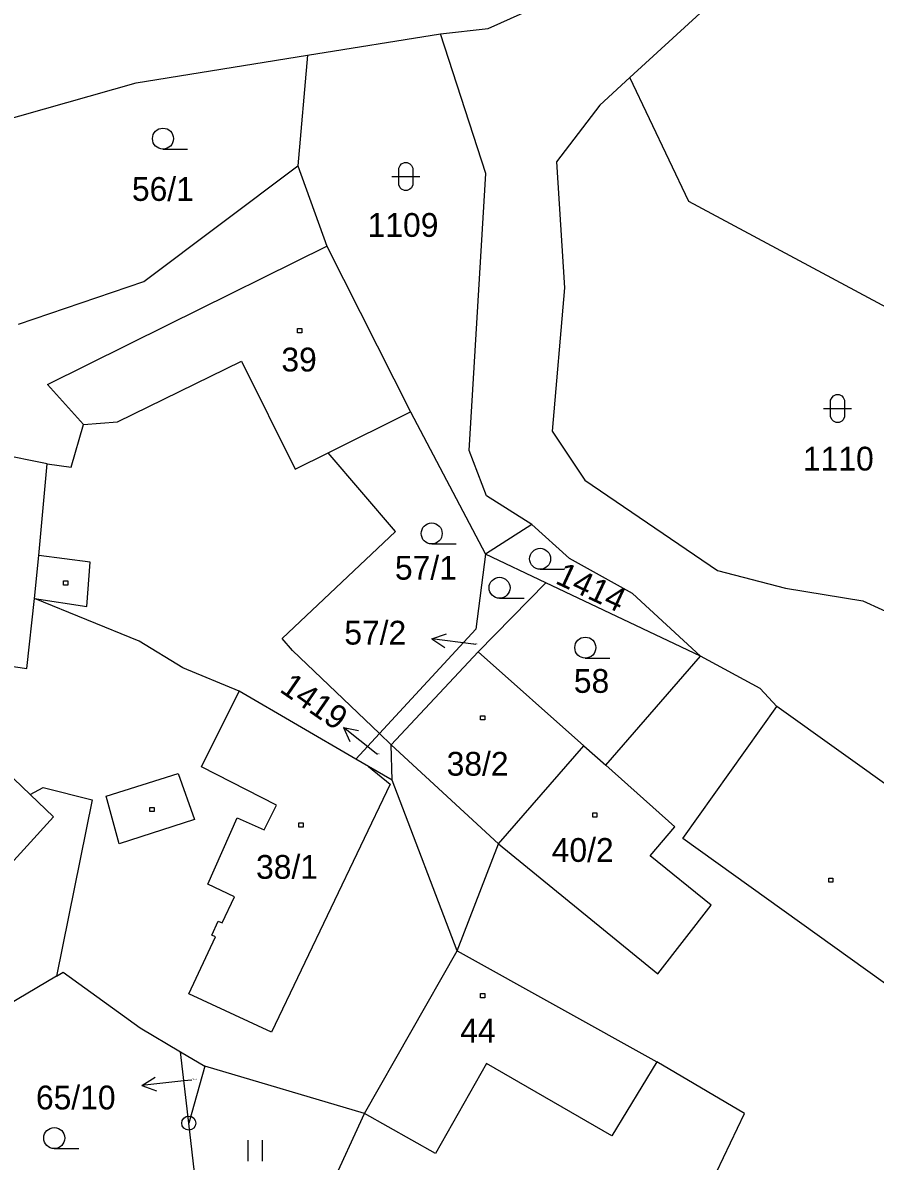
# Model space of a CAD drawing. Extents: x -796130 to -793145, y -1109506 to -1106267.
# Drawn here: x -794380.3 to -794319.4, y -1107911.5 to -1107830.1 of the extents above; entities that cross this region are included whole.
import ezdxf

# ---------------------------------------------------------------- set-up
doc = ezdxf.new("R2010")
doc.units = 0
for name, color, linetype in [('Komunikace', 7, 'Continuous'), ('Vrstva 1', 7, 'Continuous'), ('Vrstva 14', 7, 'Continuous'), ('Vrstva 15', 7, 'Continuous'), ('Vrstva 16', 7, 'Continuous'), ('Vrstva 2', 7, 'Continuous'), ('Vrstva 23', 7, 'Continuous'), ('Vrstva 25', 7, 'Continuous'), ('Vrstva 28', 7, 'Continuous')]:
    doc.layers.add(name, color=color, linetype=linetype)

msp = doc.modelspace()

# ---------------------------------------------------------------- linework, layer by layer
at = {"layer": 'Komunikace'}
for p, q in [((-794347.96, -1107874.54), (-794348.14, -1107874.52)), ((-794354.99, -1107882.39), (-794355.08, -1107882.32)), ((-794368.26, -1107905.67), (-794368.84, -1107905.73))]:
    msp.add_line(p, q, dxfattribs=at)
at = {"layer": 'Vrstva 1'}
for p, q in [((-794347.08, -1107830.5), (-794344.59, -1107829.39)), ((-794331.93, -1107829.42), (-794336.96, -1107834.02)), ((-794350.48, -1107830.89), (-794347.08, -1107830.5)), ((-794359.99, -1107832.42), (-794350.48, -1107830.89)), ((-794347.26, -1107840.88), (-794350.48, -1107830.89)), ((-794372.24, -1107834.39), (-794359.99, -1107832.42)), ((-794359.99, -1107832.42), (-794360.69, -1107840.33)), ((-794336.96, -1107834.02), (-794339.11, -1107835.98)), ((-794332.74, -1107842.87), (-794336.96, -1107834.02)), ((-794387.13, -1107838.61), (-794372.24, -1107834.39)), ((-794339.11, -1107835.98), (-794342.2, -1107840.04)), ((-794371.7, -1107848.58), (-794360.69, -1107840.33)), ((-794360.69, -1107840.33), (-794358.61, -1107846.07)), ((-794342.2, -1107840.04), (-794341.63, -1107849.04)), ((-794348.44, -1107860.66), (-794347.26, -1107840.88)), ((-794317.46, -1107851.08), (-794332.74, -1107842.87)), ((-794369.98, -1107851.7), (-794358.61, -1107846.07)), ((-794358.61, -1107846.07), (-794352.64, -1107857.91)), ((-794380.64, -1107851.64), (-794371.7, -1107848.58)), ((-794341.63, -1107849.04), (-794342.51, -1107859.28)), ((-794378.57, -1107855.95), (-794369.98, -1107851.7)), ((-794375.99, -1107858.82), (-794378.57, -1107855.95)), ((-794358.52, -1107860.84), (-794352.64, -1107857.91)), ((-794352.64, -1107857.91), (-794347.28, -1107868.09)), ((-794376.89, -1107861.87), (-794375.99, -1107858.82)), ((-794378.6, -1107861.62), (-794387.41, -1107859.84)), ((-794342.51, -1107859.28), (-794340.17, -1107862.78)), ((-794353.71, -1107866.47), (-794358.52, -1107860.84)), ((-794347.2, -1107863.9), (-794348.44, -1107860.66)), ((-794379.19, -1107868.18), (-794378.6, -1107861.62)), ((-794378.6, -1107861.62), (-794376.89, -1107861.87)), ((-794340.17, -1107862.78), (-794330.69, -1107869.24)), ((-794343.96, -1107865.95), (-794347.2, -1107863.9)), ((-794361.8, -1107874.11), (-794353.71, -1107866.47)), ((-794343.96, -1107865.95), (-794347.28, -1107868.09)), ((-794341.28, -1107868.4), (-794343.96, -1107865.95)), ((-794379.5, -1107871.25), (-794379.19, -1107868.18)), ((-794342.97, -1107870.13), (-794347.28, -1107868.09)), ((-794336.76, -1107870.88), (-794341.28, -1107868.4)), ((-794330.69, -1107869.24), (-794325.84, -1107870.51)), ((-794347.79, -1107875.06), (-794342.97, -1107870.13)), ((-794331.92, -1107875.38), (-794342.97, -1107870.13)), ((-794325.84, -1107870.51), (-794320.31, -1107871.41)), ((-794380.04, -1107876.26), (-794379.5, -1107871.25)), ((-794372.02, -1107874.29), (-794379.5, -1107871.25)), ((-794331.92, -1107875.38), (-794336.76, -1107870.88)), ((-794320.31, -1107871.41), (-794314.42, -1107874.11)), ((-794368.91, -1107876.2), (-794372.02, -1107874.29)), ((-794361.07, -1107874.97), (-794361.8, -1107874.11)), ((-794387.27, -1107875.15), (-794380.04, -1107876.26)), ((-794354.84, -1107880.9), (-794361.07, -1107874.97)), ((-794354.01, -1107881.7), (-794347.79, -1107875.06)), ((-794347.79, -1107875.06), (-794340.25, -1107881.77)), ((-794338.68, -1107883.17), (-794331.92, -1107875.38)), ((-794327.64, -1107877.67), (-794331.92, -1107875.38)), ((-794379.8, -1107885.26), (-794389.2, -1107876.29)), ((-794364.88, -1107877.88), (-794368.91, -1107876.2)), ((-794356.53, -1107882.73), (-794364.88, -1107877.88)), ((-794326.45, -1107878.97), (-794327.64, -1107877.67)), ((-794316.94, -1107885.78), (-794326.45, -1107878.97)), ((-794354.84, -1107880.9), (-794356.53, -1107882.73)), ((-794354.01, -1107881.7), (-794354.84, -1107880.9)), ((-794353.95, -1107884.23), (-794354.01, -1107881.7)), ((-794346.35, -1107888.77), (-794340.25, -1107881.77)), ((-794340.25, -1107881.77), (-794338.68, -1107883.17)), ((-794355.63, -1107883.26), (-794356.53, -1107882.73)), ((-794353.95, -1107884.23), (-794355.63, -1107883.26)), ((-794349.3, -1107896.42), (-794353.95, -1107884.23)), ((-794379.8, -1107885.26), (-794378.88, -1107884.76)), ((-794378.88, -1107884.76), (-794375.38, -1107885.63)), ((-794375.38, -1107885.63), (-794377.92, -1107898.25)), ((-794349.3, -1107896.42), (-794346.35, -1107888.77)), ((-794355.91, -1107908.06), (-794349.3, -1107896.42)), ((-794349.3, -1107896.42), (-794335.04, -1107904.37)), ((-794377.92, -1107898.25), (-794383.71, -1107901.64)), ((-794377.92, -1107898.25), (-794377.45, -1107897.95)), ((-794377.45, -1107897.95), (-794371.95, -1107901.93)), ((-794371.95, -1107901.93), (-794369.07, -1107903.65)), ((-794368.48, -1107908.74), (-794369.07, -1107903.65)), ((-794369.07, -1107903.65), (-794367.34, -1107904.68)), ((-794367.34, -1107904.68), (-794368.48, -1107908.74)), ((-794355.91, -1107908.06), (-794367.34, -1107904.68)), ((-794328.77, -1107908.05), (-794335.04, -1107904.37)), ((-794360.32, -1107917.58), (-794355.91, -1107908.06)), ((-794332.4, -1107915.66), (-794328.77, -1107908.05))]:
    msp.add_line(p, q, dxfattribs=at)
for points in [[(-794347.28, -1107868.09), (-794347.96, -1107873.45), (-794354.84, -1107880.9)], [(-794370.64, -1107920.8), (-794367.05, -1107921.18), (-794368.48, -1107908.74)]]:
    msp.add_lwpolyline(points, dxfattribs=at)
at = {"layer": 'Vrstva 16'}
for p, q in [((-794351.115, -1107874.135), (-794350.059, -1107873.768)), ((-794348.14, -1107874.52), (-794351.115, -1107874.135)), ((-794351.115, -1107874.135), (-794350.187, -1107874.759)), ((-794355.08, -1107882.32), (-794357.431, -1107880.457)), ((-794357.431, -1107880.457), (-794356.958, -1107881.47)), ((-794357.431, -1107880.457), (-794356.337, -1107880.686)), ((-794371.822, -1107906.056), (-794370.882, -1107905.45)), ((-794368.84, -1107905.73), (-794371.822, -1107906.056)), ((-794371.822, -1107906.056), (-794370.773, -1107906.444))]:
    msp.add_line(p, q, dxfattribs=at)
at = {"layer": 'Vrstva 2'}
for p, q in [((-794373.57, -1107858.63), (-794364.7, -1107854.28)), ((-794364.7, -1107854.28), (-794360.87, -1107862.01)), ((-794375.99, -1107858.82), (-794373.57, -1107858.63)), ((-794360.87, -1107862.01), (-794358.52, -1107860.84)), ((-794375.52, -1107868.66), (-794379.19, -1107868.18)), ((-794375.77, -1107871.81), (-794375.52, -1107868.66)), ((-794379.5, -1107871.25), (-794375.77, -1107871.81)), ((-794367.57, -1107883.28), (-794364.88, -1107877.88)), ((-794333.17, -1107888.4), (-794326.45, -1107878.97)), ((-794346.35, -1107888.77), (-794354.01, -1107881.7)), ((-794362.2, -1107886.02), (-794367.57, -1107883.28)), ((-794355.63, -1107883.26), (-794354.08, -1107884.51)), ((-794333.74, -1107887.56), (-794338.68, -1107883.17)), ((-794374.38, -1107885.37), (-794369.23, -1107883.76)), ((-794369.23, -1107883.76), (-794368.07, -1107887.05)), ((-794378.14, -1107886.86), (-794379.8, -1107885.26)), ((-794354.08, -1107884.51), (-794362.57, -1107902.25)), ((-794373.45, -1107888.77), (-794374.38, -1107885.37)), ((-794363.1, -1107887.78), (-794362.2, -1107886.02)), ((-794383.35, -1107892.55), (-794378.14, -1107886.86)), ((-794368.07, -1107887.05), (-794373.45, -1107888.77)), ((-794367.11, -1107891.66), (-794365.01, -1107886.93)), ((-794365.01, -1107886.93), (-794363.1, -1107887.78)), ((-794335.51, -1107889.65), (-794333.74, -1107887.56)), ((-794312.5, -1107903.24), (-794333.17, -1107888.4)), ((-794346.35, -1107888.77), (-794334.95, -1107898.06)), ((-794331.15, -1107893.16), (-794335.51, -1107889.65)), ((-794365.2, -1107892.56), (-794367.11, -1107891.66)), ((-794366.08, -1107894.43), (-794365.2, -1107892.56)), ((-794334.95, -1107898.06), (-794331.15, -1107893.16)), ((-794366.84, -1107895.3), (-794366.37, -1107894.3)), ((-794366.37, -1107894.3), (-794366.08, -1107894.43)), ((-794368.47, -1107899.49), (-794366.56, -1107895.43)), ((-794366.56, -1107895.43), (-794366.84, -1107895.3)), ((-794362.57, -1107902.25), (-794368.47, -1107899.49)), ((-794347.21, -1107904.49), (-794350.84, -1107910.91)), ((-794338.24, -1107909.65), (-794347.21, -1107904.49)), ((-794335.04, -1107904.37), (-794338.24, -1107909.65)), ((-794350.84, -1107910.91), (-794355.91, -1107908.06))]:
    msp.add_line(p, q, dxfattribs=at)
at = {"layer": 'Vrstva 23'}
for p, q in [((-794370.32, -1107839.13), (-794368.57, -1107839.13)), ((-794353.47, -1107840.49), (-794353.37, -1107840.29)), ((-794353.47, -1107841.69), (-794353.47, -1107840.49)), ((-794353.37, -1107840.29), (-794353.27, -1107840.19)), ((-794353.27, -1107840.19), (-794353.07, -1107840.09)), ((-794353.07, -1107840.09), (-794352.87, -1107840.09)), ((-794352.87, -1107840.09), (-794352.67, -1107840.19)), ((-794352.67, -1107840.19), (-794352.57, -1107840.29)), ((-794352.57, -1107840.29), (-794352.47, -1107840.49)), ((-794352.47, -1107840.49), (-794352.47, -1107841.69)), ((-794353.97, -1107841.09), (-794351.97, -1107841.09)), ((-794353.37, -1107841.89), (-794353.47, -1107841.69)), ((-794353.27, -1107841.99), (-794353.37, -1107841.89)), ((-794353.07, -1107842.09), (-794353.27, -1107841.99)), ((-794352.87, -1107842.09), (-794353.07, -1107842.09)), ((-794352.67, -1107841.99), (-794352.87, -1107842.09)), ((-794352.57, -1107841.89), (-794352.67, -1107841.99)), ((-794352.47, -1107841.69), (-794352.57, -1107841.89)), ((-794322.51, -1107856.87), (-794322.41, -1107856.77)), ((-794322.41, -1107856.77), (-794322.21, -1107856.67)), ((-794322.21, -1107856.67), (-794322.01, -1107856.67)), ((-794322.01, -1107856.67), (-794321.81, -1107856.77)), ((-794321.81, -1107856.77), (-794321.71, -1107856.87)), ((-794322.61, -1107857.07), (-794322.51, -1107856.87)), ((-794322.61, -1107858.27), (-794322.61, -1107857.07)), ((-794321.71, -1107856.87), (-794321.61, -1107857.07)), ((-794321.61, -1107857.07), (-794321.61, -1107858.27)), ((-794323.11, -1107857.67), (-794321.11, -1107857.67)), ((-794322.51, -1107858.47), (-794322.61, -1107858.27)), ((-794321.61, -1107858.27), (-794321.71, -1107858.47)), ((-794322.41, -1107858.57), (-794322.51, -1107858.47)), ((-794322.21, -1107858.67), (-794322.41, -1107858.57)), ((-794322.01, -1107858.67), (-794322.21, -1107858.67)), ((-794321.81, -1107858.57), (-794322.01, -1107858.67)), ((-794321.71, -1107858.47), (-794321.81, -1107858.57)), ((-794351.12, -1107867.35), (-794349.37, -1107867.35)), ((-794343.37, -1107869.16), (-794341.62, -1107869.16)), ((-794346.27, -1107871.23), (-794344.52, -1107871.23)), ((-794340.14, -1107875.51), (-794338.39, -1107875.51)), ((-794364.23, -1107911.45), (-794364.23, -1107909.95)), ((-794363.23, -1107909.95), (-794363.23, -1107911.45)), ((-794378.09, -1107910.56), (-794376.34, -1107910.56))]:
    msp.add_line(p, q, dxfattribs=at)
for centre in [(-794370.32, -1107838.38), (-794351.12, -1107866.6), (-794343.37, -1107868.41), (-794346.27, -1107870.48), (-794340.14, -1107874.76), (-794378.09, -1107909.81)]:
    msp.add_circle(centre, 0.75, dxfattribs=at)
at = {"layer": 'Vrstva 25'}
for p, q in [((-794360.7, -1107851.96), (-794360.4, -1107851.96)), ((-794360.7, -1107852.26), (-794360.7, -1107851.96)), ((-794360.4, -1107852.26), (-794360.7, -1107852.26)), ((-794360.4, -1107851.96), (-794360.4, -1107852.26)), ((-794377.43, -1107869.99), (-794377.13, -1107869.99)), ((-794377.43, -1107870.29), (-794377.43, -1107869.99)), ((-794377.13, -1107870.29), (-794377.43, -1107870.29)), ((-794377.13, -1107869.99), (-794377.13, -1107870.29)), ((-794347.62, -1107879.63), (-794347.32, -1107879.63)), ((-794347.62, -1107879.93), (-794347.62, -1107879.63)), ((-794347.32, -1107879.93), (-794347.62, -1107879.93)), ((-794347.32, -1107879.63), (-794347.32, -1107879.93)), ((-794371.26, -1107886.18), (-794370.96, -1107886.18)), ((-794371.26, -1107886.48), (-794371.26, -1107886.18)), ((-794370.96, -1107886.48), (-794371.26, -1107886.48)), ((-794370.96, -1107886.18), (-794370.96, -1107886.48)), ((-794339.61, -1107886.57), (-794339.31, -1107886.57)), ((-794339.61, -1107886.87), (-794339.61, -1107886.57)), ((-794339.31, -1107886.87), (-794339.61, -1107886.87)), ((-794339.31, -1107886.57), (-794339.31, -1107886.87)), ((-794360.61, -1107887.29), (-794360.31, -1107887.29)), ((-794360.61, -1107887.59), (-794360.61, -1107887.29)), ((-794360.31, -1107887.59), (-794360.61, -1107887.59)), ((-794360.31, -1107887.29), (-794360.31, -1107887.59)), ((-794322.75, -1107891.23), (-794322.45, -1107891.23)), ((-794322.75, -1107891.53), (-794322.75, -1107891.23)), ((-794322.45, -1107891.53), (-794322.75, -1107891.53)), ((-794322.45, -1107891.23), (-794322.45, -1107891.53)), ((-794347.63, -1107899.48), (-794347.33, -1107899.48)), ((-794347.63, -1107899.78), (-794347.63, -1107899.48)), ((-794347.33, -1107899.78), (-794347.63, -1107899.78)), ((-794347.33, -1107899.48), (-794347.33, -1107899.78))]:
    msp.add_line(p, q, dxfattribs=at)
at = {"layer": 'Vrstva 28'}
for radius in [0.5, 0.01]:
    msp.add_circle((-794368.48, -1107908.74), radius, dxfattribs=at)

# ---------------------------------------------------------------- texts
at = {"layer": 'Vrstva 14'}
for s, height, p in [('56/1', 1.7, (-794372.54, -1107842.83)), ('1109', 1.7, (-794355.692, -1107845.4)), ('1110', 1.7, (-794324.585, -1107862.1)), ('57/1', 1.7, (-794353.746, -1107869.9)), ('57/2', 0.1, (-794348.124, -1107874.54)), ('58', 1.7, (-794340.96, -1107877.99)), ('1419', 0.1, (-794355.135, -1107882.39)), ('65/10', 0.1, (-794368.26, -1107905.67))]:
    msp.add_text(s, height=height, dxfattribs=at).set_placement(p)
msp.add_text('1414', height=1.7, rotation=334.96101, dxfattribs=at).set_placement((-794342.364, -1107870.13))
at = {"layer": 'Vrstva 15'}
for s, p in [('39', (-794361.86, -1107855.02)), ('38/2', (-794350.05, -1107883.91)), ('40/2', (-794342.54, -1107890.07)), ('38/1', (-794363.67, -1107891.28)), ('44', (-794349.08, -1107902.98))]:
    msp.add_text(s, height=1.7, dxfattribs=at).set_placement(p)
at = {"layer": 'Vrstva 16'}
for s, p in [('57/2', (-794357.363, -1107874.54)), ('65/10', (-794379.398, -1107907.76))]:
    msp.add_text(s, height=1.7, dxfattribs=at).set_placement(p)
msp.add_text('1419', height=1.7, rotation=325.22814, dxfattribs=at).set_placement((-794362.066, -1107877.855))

doc.saveas('drawing.dxf')
